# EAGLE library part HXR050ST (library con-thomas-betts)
THOMAS&BETTS
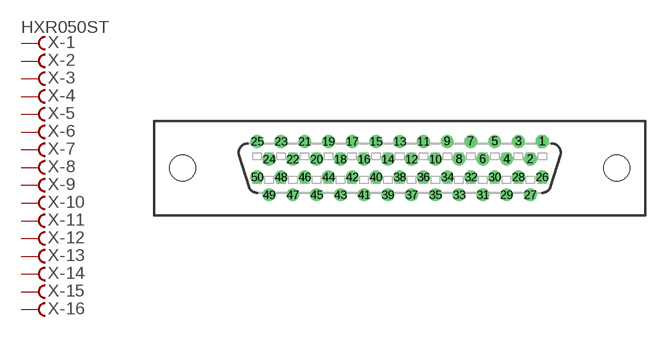
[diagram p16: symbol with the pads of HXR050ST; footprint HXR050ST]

Designator prefix X; gates -1=FV -2=F -3=F -4=F -5=F -6=F -7=F -8=F -9=F -10=F -11=F -12=F -13=F -14=F -15=F -16=F -17=F -18=F -19=F -20=F -21=F -22=F -23=F -24=F -25=F -26=F -27=F -28=F -29=F -30=F -31=F -32=F -33=F -34=F -35=F -36=F -37=F -38=F -39=F -40=F -41=F -42=F -43=F -44=F -45=F -46=F -47=F -48=F -49=F -50=F

## HXR050ST (OC_FARNELL: unknown; OC_NEWARK: unknown)  [HXR050ST]
1  -1:F  pas
2  -2:F  pas
3  -3:F  pas
4  -4:F  pas
5  -5:F  pas
6  -6:F  pas
7  -7:F  pas
8  -8:F  pas
9  -9:F  pas
10  -10:F  pas
11  -11:F  pas
12  -12:F  pas
13  -13:F  pas
14  -14:F  pas
15  -15:F  pas
16  -16:F  pas
17  -17:F  pas
18  -18:F  pas
19  -19:F  pas
20  -20:F  pas
21  -21:F  pas
22  -22:F  pas
23  -23:F  pas
24  -24:F  pas
25  -25:F  pas
26  -26:F  pas
27  -27:F  pas
28  -28:F  pas
29  -29:F  pas
30  -30:F  pas
31  -31:F  pas
32  -32:F  pas
33  -33:F  pas
34  -34:F  pas
35  -35:F  pas
36  -36:F  pas
37  -37:F  pas
38  -38:F  pas
39  -39:F  pas
40  -40:F  pas
41  -41:F  pas
42  -42:F  pas
43  -43:F  pas
44  -44:F  pas
45  -45:F  pas
46  -46:F  pas
47  -47:F  pas
48  -48:F  pas
49  -49:F  pas
50  -50:F  pas

## Footprint HXR050ST (pad centres in mm)
THOMAS&BETTS HFR050ST29xx, HHR050ST29xx
drill 0.864 octagon: 1 15.24,2.857
drill 0.864 round: 2 13.97,0.953; 3 12.7,2.857; 4 11.43,0.953; 5 10.16,2.857; 6 8.89,0.953; 7 7.62,2.857; 8 6.35,0.953; 9 5.08,2.857; 10 3.81,0.953; 11 2.54,2.857; 12 1.27,0.953; 13 0,2.857; 14 -1.27,0.953; 15 -2.54,2.857; 16 -3.81,0.953; 17 -5.08,2.857; 18 -6.35,0.953; 19 -7.62,2.857; 20 -8.89,0.953; 21 -10.16,2.857; 22 -11.43,0.953; 23 -12.7,2.857; 24 -13.97,0.953; 25 -15.24,2.857; 26 15.24,-0.953; 27 13.97,-2.857; 28 12.7,-0.953; 29 11.43,-2.857; 30 10.16,-0.953; 31 8.89,-2.857; 32 7.62,-0.953; 33 6.35,-2.857; 34 5.08,-0.953; 35 3.81,-2.857; 36 2.54,-0.953; 37 1.27,-2.857; 38 0,-0.953; 39 -1.27,-2.857; 40 -2.54,-0.953; 41 -3.81,-2.857; 42 -5.08,-0.953; 43 -6.35,-2.857; 44 -7.62,-0.953; 45 -8.89,-2.857; 46 -10.16,-0.953; 47 -11.43,-2.857; 48 -12.7,-0.953; 49 -13.97,-2.857; 50 -15.24,-0.953
hole 2.769 at 23.241,0.013
hole 2.769 at -23.241,0.013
